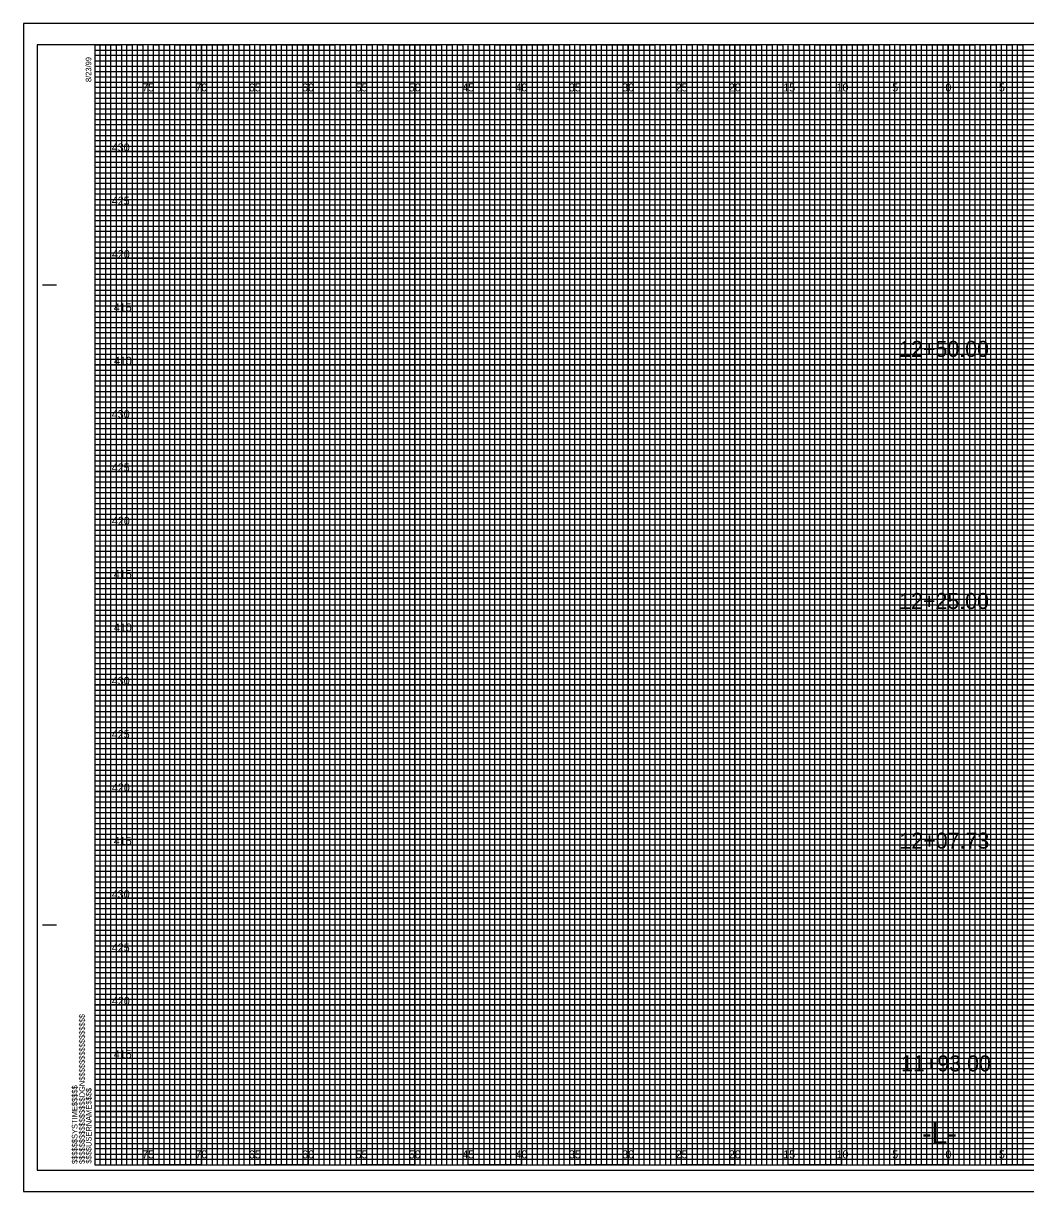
# Model space of a CAD drawing. Extents: x -7 to 181, y -2 to 107.
# Drawn here: x -6.7 to 87.2, y -2.5 to 107 of the extents above; entities that cross this region are included whole.
import ezdxf

# ---------------------------------------------------------------- set-up
doc = ezdxf.new("R2010")
doc.units = 0
for name, color, linetype in [('Prop XS Alignment Label', 7, 'Continuous'), ('Prop XS Elevation Labels', 7, 'Continuous'), ('Prop XS Offset Labels', 7, 'Continuous'), ('Prop XS Station Labels', 7, 'Continuous'), ('Sheet Cross Section CELL', 7, 'Continuous'), ('Sheet Cross Section Grid Major CELL', 7, 'Continuous'), ('Sheet Cross Section Grid Middle CELL', 7, 'Continuous'), ('Sheet Cross Section Grid Minor 1 CELL', 7, 'Continuous'), ('Sheet Cross Section Grid Minor 2 CELL', 7, 'Continuous'), ('Sheet Cutting Line CELL', 7, 'Continuous'), ('Sheet DOT Grid CELL', 7, 'Continuous'), ('Sheet Plot Border Inside CELL', 7, 'Continuous'), ('Sheet Plot Border Outside CELL', 7, 'Continuous')]:
    doc.layers.add(name, color=color, linetype=linetype)

msp = doc.modelspace()

# ---------------------------------------------------------------- linework, layer by layer
at = {"layer": 'Sheet Cross Section CELL'}
for p, q in [((-4.9, 82.5), (-3.65, 82.5)), ((-4.85, 82.5), (-3.6, 82.5)), ((-4.9, 22.5), (-3.65, 22.5)), ((-4.85, 22.5), (-3.6, 22.5)), ((0, 0), (0, 0)), ((0, 0), (0, 0)), ((0, 0), (0, 0)), ((0, 0), (0, 0)), ((0, 0), (0, 0)), ((0, 0), (0, 0)), ((0, 0), (0, 0))]:
    msp.add_line(p, q, dxfattribs=at)
msp.add_lwpolyline([(160, 105), (0, 105), (0, 0), (160, 0)], close=True, dxfattribs=at)
at = {"layer": 'Sheet Cross Section Grid Major CELL'}
for p, q in [((5, 105), (0, 105)), ((5, 0), (5, 105)), ((15, 105), (10, 105)), ((10, 105), (10, 0)), ((15, 0), (15, 105)), ((25, 105), (20, 105)), ((20, 105), (20, 0)), ((25, 0), (25, 105)), ((35, 105), (30, 105)), ((30, 105), (30, 0)), ((35, 0), (35, 105)), ((45, 105), (40, 105)), ((40, 105), (40, 0)), ((45, 0), (45, 105)), ((55, 105), (50, 105)), ((50, 105), (50, 0)), ((55, 0), (55, 105)), ((65, 105), (60, 105)), ((60, 105), (60, 0)), ((65, 0), (65, 105)), ((75, 105), (70, 105)), ((70, 105), (70, 0)), ((75, 0), (75, 105)), ((85, 105), (80, 105)), ((80, 105), (80, 0)), ((85, 0), (85, 105)), ((10, 0), (5, 0)), ((20, 0), (15, 0)), ((30, 0), (25, 0)), ((40, 0), (35, 0)), ((50, 0), (45, 0)), ((60, 0), (55, 0)), ((70, 0), (65, 0)), ((80, 0), (75, 0)), ((90, 0), (85, 0))]:
    msp.add_line(p, q, dxfattribs=at)
for points in [[(0, 100), (160, 100), (160, 95), (0, 95)], [(0, 90), (160, 90), (160, 85), (0, 85)], [(0, 80), (160, 80), (160, 75), (0, 75)], [(0, 70), (160, 70), (160, 65), (0, 65)], [(0, 60), (160, 60), (160, 55), (0, 55)], [(0, 50), (160, 50), (160, 45), (0, 45)], [(0, 40), (160, 40), (160, 35), (0, 35)], [(0, 30), (160, 30), (160, 25), (0, 25)], [(0, 20), (160, 20), (160, 15), (0, 15)], [(0, 10), (160, 10), (160, 5), (0, 5)]]:
    msp.add_lwpolyline(points, dxfattribs=at)
at = {"layer": 'Sheet Cross Section Grid Middle CELL'}
for points in [[(0, 105), (2.5, 105), (2.5, 0), (7.5, 0), (7.5, 105), (12.5, 105), (12.5, 0), (17.5, 0), (17.5, 105), (22.5, 105), (22.5, 0), (27.5, 0), (27.5, 105), (32.5, 105), (32.5, 0), (37.5, 0), (37.5, 105), (42.5, 105), (42.5, 0), (47.5, 0), (47.5, 105), (52.5, 105), (52.5, 0), (57.5, 0), (57.5, 105), (62.5, 105), (62.5, 0), (67.5, 0), (67.5, 105), (72.5, 105), (72.5, 0), (77.5, 0), (77.5, 105), (82.5, 105), (82.5, 0), (87.5, 0)], [(0, 102.5), (137.5, 102.5)], [(0, 92.5), (160, 92.5), (160, 97.5), (0, 97.5)], [(0, 82.5), (160, 82.5), (160, 87.5), (0, 87.5)], [(0, 72.5), (160, 72.5), (160, 77.5), (0, 77.5)], [(0, 62.5), (160, 62.5), (160, 67.5), (0, 67.5)], [(0, 52.5), (160, 52.5), (160, 57.5), (0, 57.5)], [(0, 42.5), (160, 42.5), (160, 47.5), (0, 47.5)], [(0, 32.5), (160, 32.5), (160, 37.5), (0, 37.5)], [(0, 22.5), (160, 22.5), (160, 27.5), (0, 27.5)], [(0, 12.5), (160, 12.5), (160, 17.5), (0, 17.5)], [(0, 2.5), (160, 2.5), (160, 7.5), (0, 7.5)]]:
    msp.add_lwpolyline(points, dxfattribs=at)
at = {"layer": 'Sheet Cross Section Grid Minor 1 CELL'}
for p, q in [((0, 104.5), (130, 104.5)), ((130, 103.99), (0, 103.99)), ((0, 103.99), (0, 103.5)), ((0, 103.5), (130, 103.5)), ((130, 102.95), (0, 102.95)), ((0, 102.95), (0, 102)), ((0, 102), (160, 102))]:
    msp.add_line(p, q, dxfattribs=at)
for points in [[(0, 101.5), (135, 101.5), (160, 101.5), (160, 101), (0, 101)], [(0, 100.5), (160, 100.5), (160, 99.5), (0, 99.5)], [(0, 99), (160, 99), (160, 98.5), (0, 98.49)], [(0, 98), (160, 98), (160, 97), (0, 97)], [(0, 96.5), (160, 96.5), (160, 96), (0, 96)], [(0, 95.5), (160, 95.5), (160, 94.5), (0, 94.5)], [(0, 94), (160, 94), (160, 93.5), (0, 93.5)], [(0, 93), (160, 93), (160, 92), (0, 92)], [(0, 91.5), (160, 91.5), (160, 91), (0, 91)], [(0, 90.5), (160, 90.5), (160, 89.5), (0, 89.5)], [(0, 89), (160, 89), (160, 88.5), (0, 88.5)], [(0, 88), (160, 88), (160, 86.98), (160, 86.5), (160, 86), (0, 86)], [(0, 87), (160, 87), (160, 86.5), (0, 86.5)], [(0, 85.5), (160, 85.5), (160, 84.5), (0, 84.52)], [(0, 84.52), (160, 84.5), (160, 84), (0, 84)], [(0, 83.5), (160, 83.5), (160, 83), (0, 83)], [(0, 82), (160, 82), (160, 81.5), (0, 81.5)], [(0, 81), (160, 81), (160, 80.5), (0, 80.5)], [(-0.04, 79.45), (160, 79.45), (160, 78.94), (-0.04, 78.94)], [(0, 78.5), (160, 78.5), (160, 78), (0, 78)], [(0, 77), (160, 77), (160, 76.5), (0, 76.5)], [(0, 76), (160, 76), (160, 75.5), (0, 75.5)], [(0, 74.5), (160, 74.5), (160, 74), (0, 74)], [(0, 73.5), (160, 73.5), (160, 73), (0, 73)], [(0, 72), (160, 72), (160, 71.5), (0, 71.5)], [(0, 71), (160, 71), (160, 70.5), (0, 70.5)], [(0, 69.5), (160, 69.5), (160, 68.99), (0, 69)], [(0, 68.5), (160, 68.5), (160, 68), (0, 68)], [(0, 67), (160, 67), (160, 66.5), (0, 66.5)], [(0, 66), (160, 66), (160, 65.5), (0, 65.5)], [(0, 64.5), (160, 64.5), (160, 64), (0, 64)], [(0, 63.5), (160, 63.5), (160, 63), (0, 63)], [(0, 62), (160, 62), (160, 61.5), (0, 61.5)], [(0, 61), (160, 61), (160, 60.5), (0, 60.5)], [(0, 59.5), (160, 59.5), (160, 59), (0, 59)], [(0, 58.5), (160.03, 58.45), (160, 58), (0, 58)], [(0, 57), (160, 57), (160, 56.5), (0, 56.5)], [(0, 56), (160, 56), (160, 55.5), (0, 55.5)], [(0, 54.5), (160, 54.5), (160, 54), (0, 54)], [(0, 53.5), (160, 53.5), (160, 53), (0, 53)], [(0, 52), (160, 52), (160, 51.5), (0, 51.5)], [(0, 51), (160, 51), (160, 50.5), (0, 50.5)], [(0, 49.5), (160, 49.5), (160, 49), (0, 49)], [(0, 48.5), (160, 48.5), (160, 48), (0, 48)], [(0, 47), (160, 47), (160, 46.5), (0, 46.5)], [(0, 46), (160, 46), (160, 45.5), (0, 45.5)], [(0, 44.5), (160, 44.5), (160, 44), (0, 44)], [(0, 43.5), (160, 43.5), (160, 43), (0, 43)], [(0, 42), (160, 42), (160, 41.5), (0, 41.5)], [(0, 41), (160, 41), (160, 40.5), (0, 40.5)], [(0, 39.5), (160, 39.5), (160, 38.99), (0, 39)], [(0, 38.5), (160, 38.5), (160, 38), (0, 38)], [(0, 37), (160, 37), (160, 36.5), (0, 36.5)], [(0, 36), (160, 36), (160, 35.5), (0, 35.5)], [(0, 34.5), (160, 34.5), (160, 34), (0, 34)], [(0, 33.5), (160, 33.5), (160, 33), (0, 33)], [(0, 32), (160, 32), (160, 31.5), (0, 31.5)], [(0, 31), (160, 31), (160, 30.5), (0, 30.5)], [(0, 29.5), (160, 29.5), (160, 29), (0, 29)], [(0, 28.5), (160.03, 28.46), (160, 28), (0, 28)], [(0, 27), (160, 27), (160, 26.5), (0, 26.5)], [(0, 26), (160, 26), (160, 25.5), (0, 25.5)], [(0, 24.5), (160, 24.5), (160, 24), (0, 24)], [(0, 23.5), (160, 23.5), (160, 23), (0, 23)], [(0, 22), (160, 22), (160, 21.5), (0, 21.5)], [(0, 21), (160, 21), (160, 20.5), (0, 20.5)], [(0, 19.5), (160, 19.5), (160, 19), (0, 19)], [(0, 18.5), (160, 18.5), (160, 18), (0, 18)], [(0, 17), (160, 17), (160, 16.5), (0, 16.5)], [(0, 16), (160, 16), (160, 15.5), (0, 15.5)], [(0, 14.5), (160, 14.5), (160, 14), (0, 14)], [(0, 13.5), (160, 13.5), (160, 13), (0, 13)], [(0, 12), (160, 12), (160, 11.5), (0, 11.5)], [(0, 11), (160, 11), (160, 10.5), (0, 10.5)], [(0, 9.5), (160, 9.5), (160, 9), (0, 9)], [(0, 8.5), (160, 8.5), (160, 8), (0, 8)], [(0, 7), (160, 7), (160, 6.5), (0, 6.5)], [(0, 6), (160, 6), (160, 5.5), (0, 5.5)], [(0, 4.5), (160, 4.5), (160, 4), (0, 4)], [(0, 3.5), (160, 3.5), (160, 3), (0, 3)], [(0, 2), (160, 2), (160, 1.5), (0, 1.5)], [(0, 1), (160, 1), (160, 0.5), (0, 0.5)]]:
    msp.add_lwpolyline(points, dxfattribs=at)
at = {"layer": 'Sheet Cross Section Grid Minor 2 CELL'}
for points in [[(0, 0), (0.5, 0), (0.5, 105), (1, 105), (1, 0)], [(1, 0), (1.5, 0), (1.5, 105), (2, 105), (2, 0)], [(2.5, 0), (3, 0), (3, 105), (3.5, 105), (3.5, 0)], [(3.5, 0), (4, 0), (4, 105), (4.5, 105), (4.5, 0)], [(5, 0), (5.5, 0), (5.5, 105), (6, 105), (6, 0)], [(6, 0), (6.5, 0), (6.5, 105), (7, 105), (7, 0)], [(7.5, 0), (8, 0), (8, 105), (8.5, 105), (8.5, 0)], [(8.5, 0), (9, 0), (9, 105), (9.5, 105), (9.5, 0)], [(10, 0), (10.5, 0), (10.5, 105), (11, 105), (11, 0)], [(11, 0), (11.5, 0), (11.5, 105), (12, 105), (12, 0)], [(12.5, 0), (13, 0), (13, 105), (13.5, 105), (13.5, 0)], [(13.5, 0), (14, 0), (14, 105), (14.5, 105), (14.5, 0)], [(15, 0), (15.5, 0), (15.5, 105), (16, 105), (16, 0)], [(16, 0), (16.5, 0), (16.5, 105), (17, 105), (17, 0)], [(17.5, 0), (18, 0), (18, 105), (18.5, 105), (18.5, 0)], [(18.5, 0), (19, 0), (19, 105), (19.5, 105), (19.5, 0)], [(20, 0), (20.5, 0), (20.5, 105), (21, 105), (21, 0)], [(21, 0), (21.5, 0), (21.5, 105), (22, 105), (22, 0)], [(22.5, 0), (23, 0), (23, 105), (23.5, 105), (23.5, 0)], [(23.5, 0), (24, 0), (24, 105), (24.5, 105), (24.5, 0)], [(25, 0), (25.5, 0), (25.5, 105), (26, 105), (26, 0)], [(26, 0), (26.5, 0), (26.5, 105), (27, 105), (27, 0)], [(27.5, 0), (28, 0), (28, 105), (28.5, 105), (28.5, 0)], [(28.5, 0), (29, 0), (29, 105), (29.5, 105), (29.5, 0)], [(30, 0), (30.5, 0), (30.5, 105), (31, 105), (31, 0)], [(31, 0), (31.5, 0), (31.5, 105), (32, 105), (32, 0)], [(32.5, 0), (33, 0), (33, 105), (33.5, 105), (33.5, 0)], [(33.5, 0), (34, 0), (34, 105), (34.5, 105), (34.5, 0)], [(35, 0), (35.5, 0), (35.5, 105), (36, 105), (36, 0)], [(36, 0), (36.5, 0), (36.5, 105), (37, 105), (37, 0)], [(37.5, 0), (38, 0), (38, 105), (38.5, 105), (38.5, 0)], [(38.5, 0), (39, 0), (39, 105), (39.5, 105), (39.5, 0)], [(40, 0), (40.5, 0), (40.5, 105), (41, 105), (41, 0)], [(41, 0), (41.5, 0), (41.5, 105), (42, 105), (42, 0)], [(42.5, 0), (43, 0), (43, 105), (43.5, 105), (43.5, 0)], [(43.5, 0), (44, 0), (44, 105), (44.5, 105), (44.5, 0)], [(45, 0), (45.5, 0), (45.5, 105), (46, 105), (46, 0)], [(46, 0), (46.5, 0), (46.5, 105), (47, 105), (47, 0)], [(47.5, 0), (48, 0), (48, 105), (48.5, 105), (48.5, 0)], [(48.5, 0), (49, 0), (49, 105), (49.5, 105), (49.5, 0)], [(50, 0), (50.5, 0), (50.5, 105), (51, 105), (51, 0)], [(51, 0), (51.5, 0), (51.5, 105), (52, 105), (52, 0)], [(52.5, 0), (53, 0), (53, 105), (53.5, 105), (53.5, 0)], [(53.5, 0), (54, 0), (54, 105), (54.5, 105), (54.5, 0)], [(55, 0), (55.5, 0), (55.5, 105), (56, 105), (56, 0)], [(56, 0), (56.5, 0), (56.5, 105), (57, 105), (57, 0)], [(57.5, 0), (58, 0), (58, 105), (58.5, 105), (58.5, 0)], [(58.5, 0), (59, 0), (59, 105), (59.5, 105), (59.5, 0)], [(60, 0), (60.5, 0), (60.5, 105), (61, 105), (61, 0)], [(61, 0), (61.5, 0), (61.5, 105), (62, 105), (62, 0)], [(62.5, 0), (63, 0), (63, 105), (63.5, 105), (63.5, 0)], [(63.5, 0), (64, 0), (64, 105), (64.5, 105), (64.5, 0)], [(65, 0), (65.5, 0), (65.5, 105), (66, 105), (66, 0)], [(66, 0), (66.5, 0), (66.5, 105), (67, 105), (67, 0)], [(67.5, 0), (68, 0), (68, 105), (68.5, 105), (68.5, 0)], [(68.5, 0), (69, 0), (69, 105), (69.5, 105), (69.5, 0)], [(70, 0), (70.5, 0), (70.5, 105), (71, 105), (71, 0)], [(71, 0), (71.5, 0), (71.5, 105), (72, 105), (72, 0)], [(72.5, 0), (73, 0), (73, 105), (73.5, 105), (73.5, 0)], [(73.5, 0), (74, 0), (74, 105), (74.5, 105), (74.5, 0)], [(75, 0), (75.5, 0), (75.5, 105), (76, 105), (76, 0)], [(76, 0), (76.5, 0), (76.5, 105), (77, 105), (77, 0)], [(77.5, 0), (78, 0), (78, 105), (78.5, 105), (78.5, 0)], [(78.5, 0), (79, 0), (79, 105), (79.5, 105), (79.5, 0)], [(80, 0), (80.5, 0), (80.5, 105), (81, 105), (81, 0)], [(81, 0), (81.5, 0), (81.5, 105), (82, 105), (82, 0)], [(82.5, 0), (83, 0), (83, 105), (83.5, 105), (83.5, 0)], [(83.5, 0), (84, 0), (84, 105), (84.5, 105), (84.5, 0)], [(85, 0), (85.5, 0), (85.5, 105), (86, 105), (86, 0)], [(86, 0), (86.5, 0), (86.5, 105), (87, 105), (87, 0)]]:
    msp.add_lwpolyline(points, dxfattribs=at)
at = {"layer": 'Sheet Cutting Line CELL'}
for p, q in [((161.65, 107), (-6.7, 107)), ((-6.7, 107), (-6.7, -2.5)), ((-6.7, -2.5), (161.65, -2.5))]:
    msp.add_line(p, q, dxfattribs=at)
at = {"layer": 'Sheet DOT Grid CELL'}
for p, q in [((5, 0), (5, 105)), ((10, 0), (10, 105)), ((15, 0), (15, 105)), ((20, 0), (20, 105)), ((25, 0), (25, 105)), ((30, 0), (30, 105)), ((35, 0), (35, 105)), ((40, 0), (40, 105)), ((45, 0), (45, 105)), ((50, 0), (50, 105)), ((55, 0), (55, 105)), ((60, 0), (60, 105)), ((65, 0), (65, 105)), ((70, 0), (70, 105)), ((75, 0), (75, 105)), ((80, 0), (80, 105)), ((85, 0), (85, 105)), ((0, 100), (160, 100)), ((0, 95), (160, 95)), ((0, 90), (160, 90)), ((0, 85), (160, 85)), ((0, 80), (160, 80)), ((0, 75), (160, 75)), ((0, 70), (160, 70)), ((0, 65), (160, 65)), ((0, 60), (160, 60)), ((0, 55), (160, 55)), ((0, 50), (160, 50)), ((0, 45), (160, 45)), ((0, 40), (160, 40)), ((0, 35), (160, 35)), ((0, 30), (160, 30)), ((0, 25), (160, 25)), ((0, 20), (160, 20)), ((0, 15), (160, 15)), ((0, 10), (160, 10)), ((0, 5), (160, 5))]:
    msp.add_line(p, q, dxfattribs=at)
at = {"layer": 'Sheet Plot Border Inside CELL'}
msp.add_lwpolyline([(-5.4, -0.5), (161.2, -0.5), (161.2, 105), (-5.4, 105)], close=True, dxfattribs=at)
at = {"layer": 'Sheet Plot Border Outside CELL'}
msp.add_lwpolyline([(-6.7, -2.5), (161.65, -2.5), (161.65, 107), (-6.7, 107)], close=True, dxfattribs=at)

# ---------------------------------------------------------------- texts
at = {"layer": 'Prop XS Alignment Label'}
msp.add_text('-L-', height=2, dxfattribs=at).set_placement((77.53, 2))
at = {"layer": 'Prop XS Elevation Labels'}
for s, p in [('430', (1.59, 95)), ('425', (1.59, 90)), ('420', (1.6, 85)), ('415', (1.78, 80)), ('410', (1.79, 75)), ('430', (1.59, 70)), ('425', (1.59, 65)), ('420', (1.6, 60)), ('415', (1.78, 55)), ('410', (1.79, 50)), ('430', (1.59, 45)), ('425', (1.59, 40)), ('420', (1.6, 35)), ('415', (1.78, 30)), ('430', (1.59, 25)), ('425', (1.59, 20)), ('420', (1.6, 15)), ('415', (1.78, 10))]:
    msp.add_text(s, height=0.75, dxfattribs=at).set_placement(p)
at = {"layer": 'Prop XS Offset Labels'}
for s, p in [('75', (4.44, 100.62)), ('70', (9.43, 100.62)), ('65', (14.44, 100.62)), ('60', (19.43, 100.62)), ('55', (24.44, 100.62)), ('50', (29.43, 100.62)), ('45', (34.44, 100.62)), ('40', (39.43, 100.62)), ('35', (44.44, 100.62)), ('30', (49.43, 100.62)), ('25', (54.44, 100.62)), ('20', (59.43, 100.62)), ('15', (64.53, 100.62)), ('10', (69.52, 100.62)), ('5', (74.74, 100.62)), ('0', (79.73, 100.62)), ('0', (79.73, 100.62)), ('5', (84.74, 100.62)), ('75', (4.44, 0.62)), ('70', (9.43, 0.62)), ('65', (14.44, 0.62)), ('60', (19.43, 0.62)), ('55', (24.44, 0.62)), ('50', (29.43, 0.62)), ('45', (34.44, 0.62)), ('40', (39.43, 0.62)), ('35', (44.44, 0.62)), ('30', (49.43, 0.62)), ('25', (54.44, 0.62)), ('20', (59.43, 0.62)), ('15', (64.53, 0.62)), ('10', (69.52, 0.62)), ('5', (74.74, 0.62)), ('0', (79.73, 0.62)), ('0', (79.73, 0.62)), ('5', (84.74, 0.62))]:
    msp.add_text(s, height=0.75, dxfattribs=at).set_placement(p)
at = {"layer": 'Prop XS Station Labels'}
for s, p in [('12+50.00', (75.39, 75.74)), ('12+25.00', (75.39, 52.11)), ('12+07.73', (75.42, 29.65)), ('11+93.00', (75.57, 8.77))]:
    msp.add_text(s, height=1.5, dxfattribs=at).set_placement(p)
at = {"layer": 'Sheet Cross Section CELL'}
for s, p in [('8/23/99', (-0.33, 101.5)), ('$$$$$$$$$$$$$$$$DGN$$$$$$$$$$$$$$$$', (-0.94, 0.09)), ('$$$$$$SYSTIME$$$$$', (-1.63, 0.09)), ('$$$$USERNAME$$$$', (-0.31, 0.12))]:
    msp.add_text(s, height=0.525, rotation=90, dxfattribs=at).set_placement(p)

doc.saveas('drawing.dxf')
